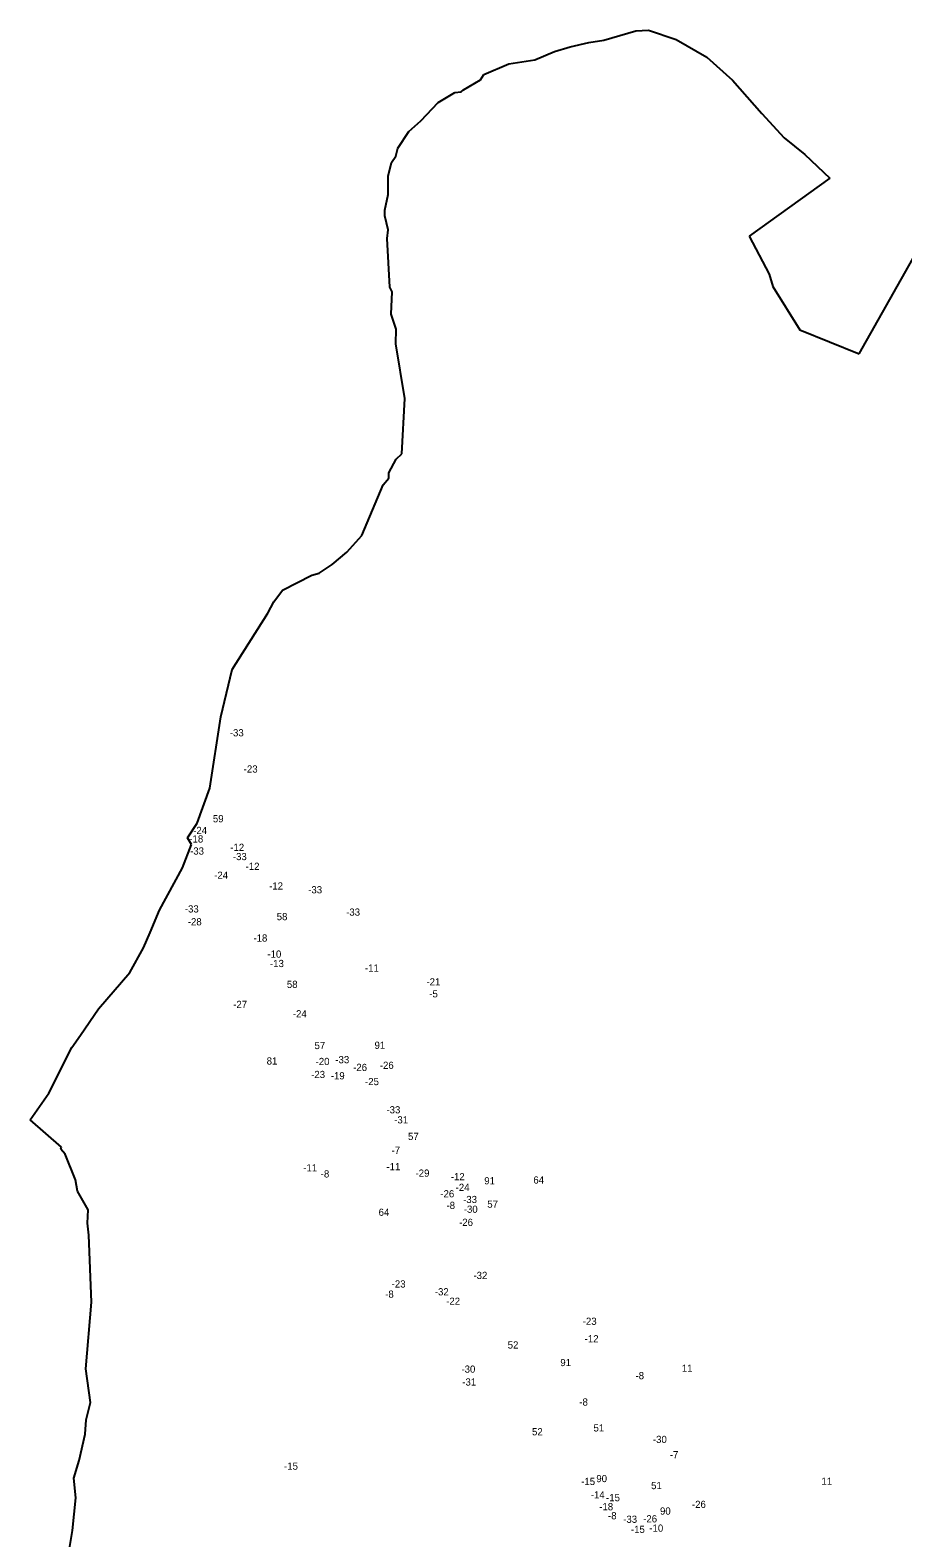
# Model space of a CAD drawing. Extents: x -772472 to -767535, y -969581 to -965387.
# Drawn here: x -772450 to -771238, y -967482 to -965387 of the extents above; entities that cross this region are included whole.
import ezdxf

# ---------------------------------------------------------------- set-up
doc = ezdxf.new("R2010")
doc.units = 0
doc.layers.add('Vrstva 13', color=7, linetype='Continuous')
doc.layers.add('Vrstva 24', color=7, linetype='Continuous')

msp = doc.modelspace()

# ---------------------------------------------------------------- linework, layer by layer
at = {"layer": 'Vrstva 13'}
for p, q in [((-771673.75, -965404.35), (-771652.96, -965401.12)), ((-771652.96, -965401.12), (-771608.74, -965387.94)), ((-771608.74, -965387.94), (-771591.17, -965387.06)), ((-771591.17, -965387.06), (-771552.81, -965400.24)), ((-771552.81, -965400.24), (-771510.05, -965424.56)), ((-771749.01, -965428.38), (-771721.77, -965416.65)), ((-771721.77, -965416.65), (-771699.81, -965410.2)), ((-771699.81, -965410.2), (-771673.75, -965404.35)), ((-771819.59, -965448.88), (-771785.03, -965433.65)), ((-771785.03, -965433.65), (-771749.01, -965428.38)), ((-771510.05, -965424.56), (-771474.33, -965456.49)), ((-771848.28, -965469.97), (-771824.27, -965455.91)), ((-771824.27, -965455.91), (-771819.59, -965448.88)), ((-771474.33, -965456.49), (-771433.62, -965502.76)), ((-771883.42, -965487.55), (-771860, -965473.78)), ((-771860, -965473.78), (-771851.21, -965472.61)), ((-771851.21, -965472.61), (-771848.28, -965469.97)), ((-771907.14, -965513.04), (-771883.42, -965487.55)), ((-771433.62, -965502.76), (-771402.8, -965536.67)), ((-771924.13, -965527.69), (-771907.14, -965513.04)), ((-771939.06, -965551.12), (-771924.13, -965527.69)), ((-771402.8, -965536.67), (-771373.81, -965559.96)), ((-771948.14, -965570.75), (-771941.99, -965562.26)), ((-771941.99, -965562.26), (-771939.06, -965551.12)), ((-771373.81, -965559.96), (-771339.25, -965592.77)), ((-771952.82, -965615.57), (-771952.53, -965589.79)), ((-771952.53, -965589.79), (-771948.14, -965570.75)), ((-771339.25, -965592.77), (-771451.19, -965673.26)), ((-771957.51, -965636.96), (-771952.82, -965615.57)), ((-771957.51, -965645.16), (-771957.51, -965636.96)), ((-771952.83, -965664.49), (-771957.51, -965645.16)), ((-771954.29, -965676.5), (-771952.83, -965664.49)), ((-771451.19, -965673.26), (-771423.67, -965725.99)), ((-771950.48, -965744.17), (-771954.29, -965676.5)), ((-771298.48, -965836.86), (-771213.27, -965685.71)), ((-771423.67, -965725.99), (-771418.39, -965742.98)), ((-771947.26, -965750.62), (-771950.48, -965744.17)), ((-771948.72, -965781.67), (-771947.26, -965750.62)), ((-771418.39, -965742.98), (-771381.06, -965803.46)), ((-771941.4, -965802.47), (-771948.72, -965781.67)), ((-771941.99, -965822.69), (-771941.4, -965802.47)), ((-771381.06, -965803.46), (-771298.48, -965836.86)), ((-771929.69, -965898.86), (-771941.99, -965822.69)), ((-771933.5, -965975.61), (-771929.69, -965898.86)), ((-771951.64, -966001.97), (-771941.69, -965982.93)), ((-771941.69, -965982.93), (-771933.5, -965975.61)), ((-771951.64, -966009.59), (-771951.64, -966001.97)), ((-771989.42, -966088.98), (-771959.84, -966018.67)), ((-771959.84, -966018.67), (-771951.64, -966009.59)), ((-772009.92, -966112.41), (-771989.42, -966088.98)), ((-772030.42, -966129.4), (-772009.92, -966112.41)), ((-772048.57, -966141.7), (-772030.42, -966129.4)), ((-772099.53, -966165.14), (-772058.82, -966144.34)), ((-772058.82, -966144.34), (-772048.57, -966141.7)), ((-772111.53, -966181.25), (-772099.53, -966165.14)), ((-772169.22, -966275.3), (-772119.73, -966197.08)), ((-772119.73, -966197.08), (-772111.53, -966181.25)), ((-772185.33, -966340.92), (-772169.22, -966275.3)), ((-772200.26, -966440.23), (-772185.33, -966340.92)), ((-772217.83, -966488.86), (-772200.26, -966440.23)), ((-772231.3, -966509.36), (-772217.83, -966488.86)), ((-772226.03, -966518.44), (-772231.3, -966509.36)), ((-772238.32, -966550.66), (-772226.03, -966518.44)), ((-772270.54, -966609.55), (-772238.32, -966550.66)), ((-772283.13, -966640.89), (-772270.54, -966609.55)), ((-772292.5, -966661.99), (-772283.13, -966640.89)), ((-772311.54, -966696.26), (-772292.5, -966661.99)), ((-772355.17, -966746.94), (-772311.54, -966696.26)), ((-772380.06, -966783.27), (-772355.17, -966746.94)), ((-772392.36, -966800.55), (-772380.06, -966783.27)), ((-772424.27, -966863.82), (-772392.36, -966800.55)), ((-772450.04, -966901.03), (-772424.27, -966863.82)), ((-772406.58, -966938.78), (-772450.04, -966901.03)), ((-772407.49, -966941.72), (-772406.58, -966938.78)), ((-772401.38, -966948.73), (-772407.49, -966941.72)), ((-772387.14, -966984.46), (-772401.38, -966948.73)), ((-772384.43, -967000.06), (-772387.14, -966984.46)), ((-772369.51, -967026.07), (-772384.43, -967000.06)), ((-772370.19, -967044.39), (-772369.51, -967026.07)), ((-772368.38, -967061.12), (-772370.19, -967044.39)), ((-772364.98, -967154.06), (-772368.38, -967061.12)), ((-772372.67, -967246.77), (-772364.98, -967154.06)), ((-772366.11, -967293.58), (-772372.67, -967246.77)), ((-772372.22, -967317.55), (-772366.11, -967293.58)), ((-772373.46, -967337.56), (-772372.22, -967317.55)), ((-772382.05, -967374.2), (-772373.46, -967337.56)), ((-772389.28, -967398.62), (-772382.05, -967374.2)), ((-772386.57, -967426.21), (-772389.28, -967398.62)), ((-772391.09, -967471.44), (-772386.57, -967426.21)), ((-772396.06, -967499.48), (-772391.09, -967471.44))]:
    msp.add_line(p, q, dxfattribs=at)

# ---------------------------------------------------------------- texts
at = {"layer": 'Vrstva 24'}
for s, p in [('-33', (-772172.67, -966368.19)), ('-23', (-772153.38, -966418.54)), ('59', (-772196.19, -966487.57)), ('-18', (-772228.934, -966515.67)), ('-24', (-772223.596, -966503.91)), ('-33', (-772227.89, -966532.51)), ('-12', (-772172.074, -966527.38)), ('-33', (-772168.45, -966540.17)), ('-12', (-772150.794, -966553.74)), ('-24', (-772194.436, -966566.13)), ('-12', (-772118.114, -966581.08)), ('-33', (-772063.76, -966586.33)), ('-33', (-772235.21, -966612.92)), ('58', (-772107.536, -966623.58)), ('-33', (-772011.08, -966617.34)), ('-28', (-772231.08, -966630.76)), ('-18', (-772139.904, -966653.37)), ('-10', (-772120.475, -966675.68)), ('-13', (-772116.924, -966688.74)), ('-11', (-771985.039, -966695.09)), ('58', (-772093.456, -966717.72)), ('-21', (-771899.554, -966714.26)), ('-5', (-771895.62, -966730.86)), ('-27', (-772168.009, -966745.61)), ('-24', (-772085.116, -966758.63)), ('57', (-772055.046, -966802.69)), ('91', (-771971.654, -966802.3)), ('81', (-772121.481, -966824.18)), ('-20', (-772053.54, -966824.86)), ('-33', (-772026.13, -966822.36)), ('-26', (-772001.394, -966833.08)), ('-26', (-771964.334, -966830.23)), ('-23', (-772059.71, -966842.93)), ('-19', (-772032.458, -966844.72)), ('-25', (-771984.86, -966852.78)), ('-33', (-771955.15, -966892.03)), ('-31', (-771944.314, -966905.94)), ('57', (-771925.156, -966928.96)), ('-7', (-771948.069, -966948.25)), ('-11', (-772070.689, -966972.58)), ('-8', (-772046.41, -966981.04)), ('-11', (-771955.169, -966971.03)), ('-29', (-771914.724, -966979.97)), ('-12', (-771865.744, -966984.91)), ('-24', (-771859.026, -966999.75)), ('91', (-771819.224, -966990.58)), ('64', (-771751.016, -966989.54)), ('-26', (-771880.244, -967008.71)), ('-33', (-771848.65, -967016.61)), ('57', (-771814.996, -967023.1)), ('64', (-771965.986, -967034.35)), ('-8', (-771871.71, -967024.85)), ('-30', (-771847.71, -967030.11)), ('-26', (-771854.194, -967048.38)), ('-32', (-771834.26, -967122.11)), ('-8', (-771956.82, -967148.12)), ('-23', (-771947.9, -967133.95)), ('-32', (-771887.89, -967144.85)), ('-22', (-771872.16, -967157.96)), ('-23', (-771682.43, -967185.76)), ('-12', (-771679.744, -967210.09)), ('52', (-771786.706, -967218.72)), ('-30', (-771850.97, -967252.28)), ('91', (-771713.554, -967243.13)), ('11', (-771544.716, -967250.95)), ('-31', (-771849.784, -967270.14)), ('-8', (-771609.12, -967261.33)), ('-8', (-771687.16, -967297.97)), ('51', (-771667.471, -967333.95)), ('52', (-771752.906, -967339.28)), ('-30', (-771584.96, -967349.94)), ('-7', (-771561.509, -967371.24)), ('-15', (-772097.354, -967387.11)), ('-15', (-771684.574, -967408.31)), ('90', (-771663.56, -967404.35)), ('51', (-771587.431, -967414.05)), ('11', (-771350.846, -967408)), ('-14', (-771671.29, -967426.92)), ('-18', (-771659.514, -967443.4)), ('-15', (-771650.064, -967430.86)), ('-26', (-771530.744, -967440.16)), ('-8', (-771647.3, -967455.97)), ('-33', (-771626.23, -967460.84)), ('-26', (-771598.504, -967460.25)), ('90', (-771575.08, -967449.44)), ('-15', (-771615.504, -967474.91)), ('-10', (-771589.915, -967473.15))]:
    msp.add_text(s, height=10, dxfattribs=at).set_placement(p)

doc.saveas('drawing.dxf')
